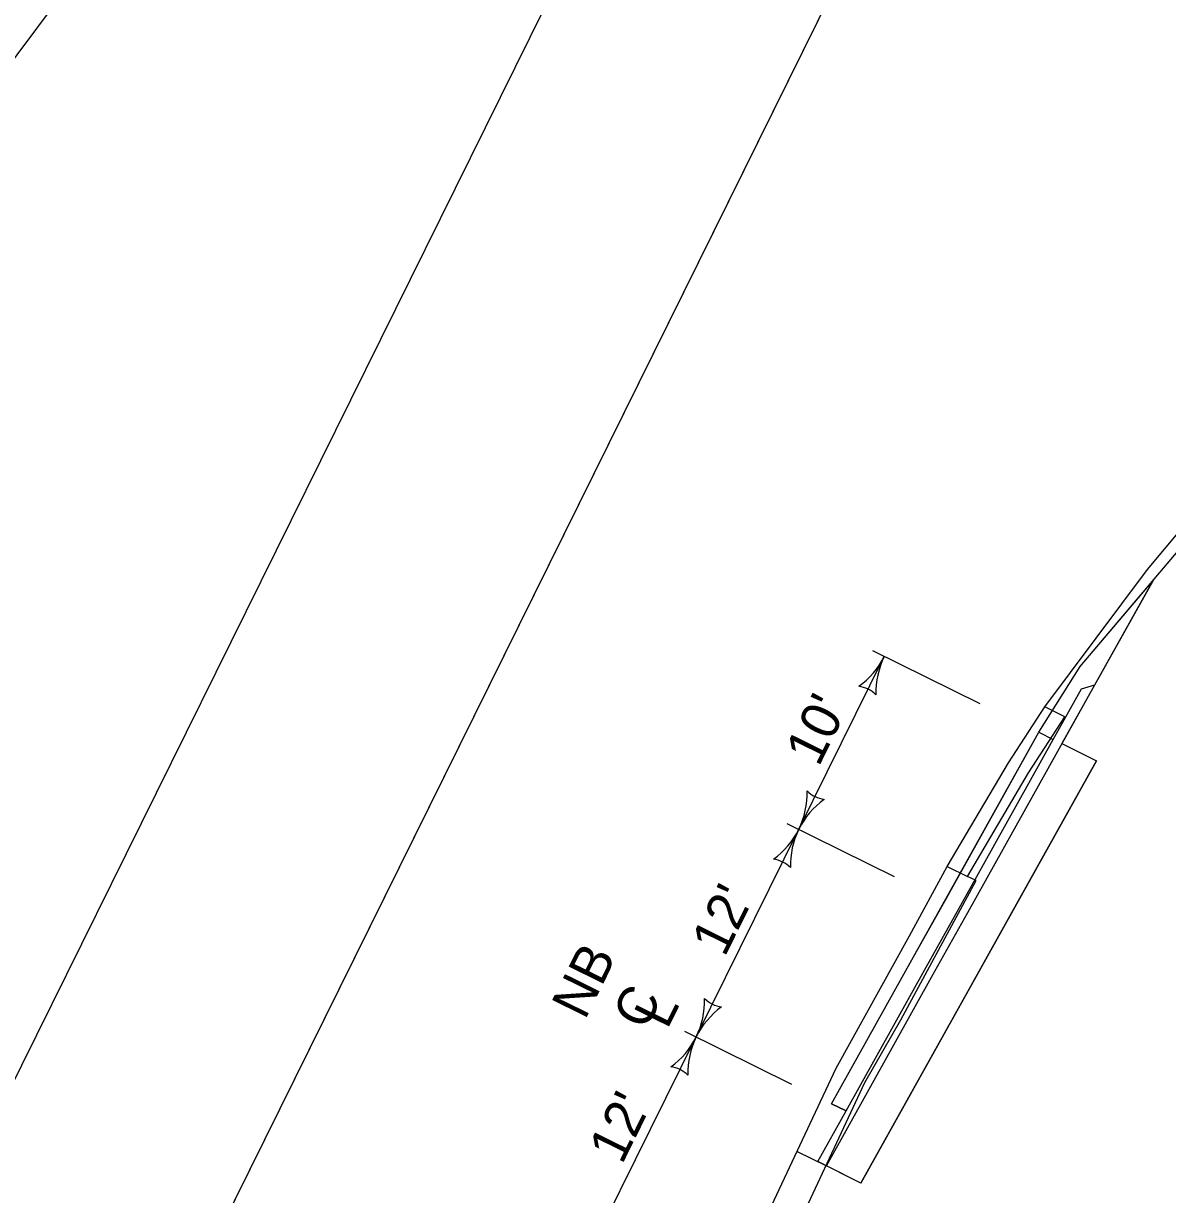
# Model space of a CAD drawing. Extents: x 14104283 to 14120882, y 8635219 to 8671666.
# Drawn here: x 14118389.3 to 14118626.5, y 8668544.6 to 8668787.4 of the extents above; entities that cross this region are included whole.
import ezdxf

# ---------------------------------------------------------------- set-up
doc = ezdxf.new("R2010")
doc.units = 0
for name, color, linetype in [('Default', 7, 'Continuous'), ('dsnCellElements', 7, 'Continuous'), ('dsnNonPlotable', 7, 'Continuous'), ('dsnShadingPaved', 7, 'Continuous'), ('dsnTextFinalPlan', 7, 'Continuous'), ('dsnTextOverlapEven', 7, 'Continuous'), ('TC_Subbase', 7, 'Continuous'), ('TC_SubgradeTreatment', 7, 'Continuous'), ('TC_SubstrataExistingPavement', 7, 'Continuous'), ('Terrain', 7, 'Continuous')]:
    doc.layers.add(name, color=color, linetype=linetype)

# ---------------------------------------------------------------- blocks, each defined once
blk = doc.blocks.new('LT')
at = {"layer": 'dsnCellElements'}
for centre, radius, start, end in [((-3.564, 0), 1.642, 342.26665, 17.73335), ((0, 4.25), 4.25, 241.92751, 270), ((0, -4.25), 4.25, 90, 118.07249)]:
    blk.add_arc(centre, radius, start, end, dxfattribs=at)

msp = doc.modelspace()

# ---------------------------------------------------------------- linework, layer by layer
at = {"layer": 'Default'}
for p, q in [((14118599.79, 8668640.48), (14118602.77, 8668639)), ((14118556.81, 8668563.44), (14118559.8, 8668561.96))]:
    msp.add_line(p, q, dxfattribs=at)
for points in [[(14118556.81, 8668563.44), (14118573.45, 8668593.27), (14118580.25, 8668605.46), (14118599.79, 8668640.48)], [(14118559.8, 8668561.96), (14118576.44, 8668591.8), (14118583.24, 8668603.98), (14118602.77, 8668639)]]:
    msp.add_lwpolyline(points, dxfattribs=at)
at = {"layer": 'dsnNonPlotable'}
msp.add_lwpolyline([(14118092.03, 8667853.71), (14118786.76, 8669258.84), (14119692.14, 8668811.2), (14118997.41, 8667406.07)], close=True, dxfattribs=at)
at = {"layer": 'dsnShadingPaved'}
msp.add_lwpolyline([(14118556.81, 8668563.44), (14118599.79, 8668640.48), (14118608.32, 8668654.13), (14118623.45, 8668671.96), (14118604.57, 8668638.11), (14118611.72, 8668634.53), (14118562.89, 8668547), (14118553.94, 8668551.46), (14118559.8, 8668561.96)], close=True, dxfattribs=at)
at = {"layer": 'dsnTextFinalPlan'}
for p, q in [((14118565.29, 8668657.42), (14118587.52, 8668646.42)), ((14118550.01, 8668620.35), (14118567.74, 8668656.2)), ((14118547.56, 8668621.56), (14118569.79, 8668610.57)), ((14118528.74, 8668577.32), (14118550.01, 8668620.35)), ((14118507.46, 8668534.29), (14118528.74, 8668577.32)), ((14118526.29, 8668578.53), (14118548.52, 8668567.54))]:
    msp.add_line(p, q, dxfattribs=at)
for points in [[(14117870.36, 8667977.42), (14118384.92, 8669018.16), (14118565.56, 8668928.85), (14118050.99, 8667888.12)], [(14118092.03, 8667853.71), (14118606.59, 8668894.44), (14118787.23, 8668805.14), (14118272.66, 8667764.4)]]:
    msp.add_lwpolyline(points, close=True, dxfattribs=at)
at = {"layer": 'dsnTextOverlapEven'}
msp.add_lwpolyline([(14117870.36, 8667977.42), (14118384.92, 8669018.16), (14118565.56, 8668928.85), (14118050.99, 8667888.12)], close=True, dxfattribs=at)
at = {"layer": 'TC_Subbase'}
for p, q in [((14118611.35, 8668650.27), (14118623.45, 8668671.96)), ((14118608.63, 8668649.5), (14118611.35, 8668650.27)), ((14118602.77, 8668639), (14118608.63, 8668649.5)), ((14118553.94, 8668551.46), (14118559.8, 8668561.96)), ((14118549.67, 8668553.58), (14118555.74, 8668550.58))]:
    msp.add_line(p, q, dxfattribs=at)
msp.add_lwpolyline([(14118555.74, 8668550.58), (14118578.23, 8668590.91), (14118585.03, 8668603.09), (14118611.35, 8668650.27)], dxfattribs=at)
at = {"layer": 'TC_SubgradeTreatment'}
for p, q in [((14118604.57, 8668638.11), (14118611.72, 8668634.53)), ((14118562.89, 8668547), (14118555.74, 8668550.58))]:
    msp.add_line(p, q, dxfattribs=at)
msp.add_lwpolyline([(14118562.89, 8668547), (14118585.39, 8668587.33), (14118592.18, 8668599.51), (14118611.72, 8668634.53)], dxfattribs=at)
at = {"layer": 'TC_SubstrataExistingPavement'}
for points in [[(14118580.77, 8668612.66), (14118584.95, 8668610.59), (14118597.65, 8668632.03), (14118605.19, 8668643.66), (14118601.01, 8668645.72)], [(14118539.47, 8668531.85), (14118545.45, 8668528.9), (14118550.55, 8668539.76), (14118563.73, 8668567.86), (14118571.18, 8668580.85), (14118586.75, 8668609.71), (14118584.95, 8668610.59)]]:
    msp.add_lwpolyline(points, dxfattribs=at)
at = {"layer": 'Terrain'}
for points in [[(14118312.3, 8668644.82), (14118315.38, 8668650.41), (14118318.4, 8668656.85), (14118336.09, 8668694.53), (14118351.32, 8668721.95), (14118359.1, 8668736.38), (14118371.8, 8668757.81), (14118379.34, 8668769.44), (14118400.6, 8668797.95), (14118408.04, 8668806.8), (14118456.58, 8668898.64)], [(14118599.79, 8668640.48), (14118608.32, 8668654.13), (14118654.78, 8668708.88), (14118678.97, 8668737.39), (14118696.75, 8668773.34), (14118700.24, 8668798.42), (14118703.85, 8668824.42)], [(14118533.97, 8668521.11), (14118537.05, 8668526.7), (14118540.07, 8668533.13), (14118557.76, 8668570.81), (14118572.99, 8668598.24), (14118580.77, 8668612.66), (14118593.46, 8668634.1), (14118601.01, 8668645.72), (14118622.27, 8668674.24), (14118629.71, 8668683.08), (14118678.25, 8668774.93)]]:
    msp.add_lwpolyline(points, dxfattribs=at)

# ---------------------------------------------------------------- block references
at = {"layer": 'dsnTextFinalPlan'}
for p, xscale, yscale, rotation in [((14118567.74, 8668656.2), 3.942400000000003, 3.9424000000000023, 63.69110745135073), ((14118550.01, 8668620.35), 3.942400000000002, 3.9424000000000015, -116.30889254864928), ((14118550.01, 8668620.35), 3.942400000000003, 3.9424000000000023, 63.69110745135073), ((14118528.74, 8668577.32), 3.942400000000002, 3.9424000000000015, -116.30889254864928), ((14118528.74, 8668577.32), 3.942400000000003, 3.9424000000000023, 63.69110745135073)]:
    msp.add_blockref('LT', p, dxfattribs=dict(at, xscale=xscale, yscale=yscale, rotation=rotation))

# ---------------------------------------------------------------- texts
for s, p in [("10'", (14118554.12, 8668633.13)), ("12'", (14118534.62, 8668593.68)), ('NB', (14118505.67, 8668580.64)), ('C', (14118518.3, 8668578.44)), ('L', (14118522.74, 8668578.69)), ("12'", (14118513.34, 8668550.66))]:
    msp.add_text(s, height=8, rotation=63.6911, dxfattribs=at).set_placement(p)

doc.saveas('drawing.dxf')
